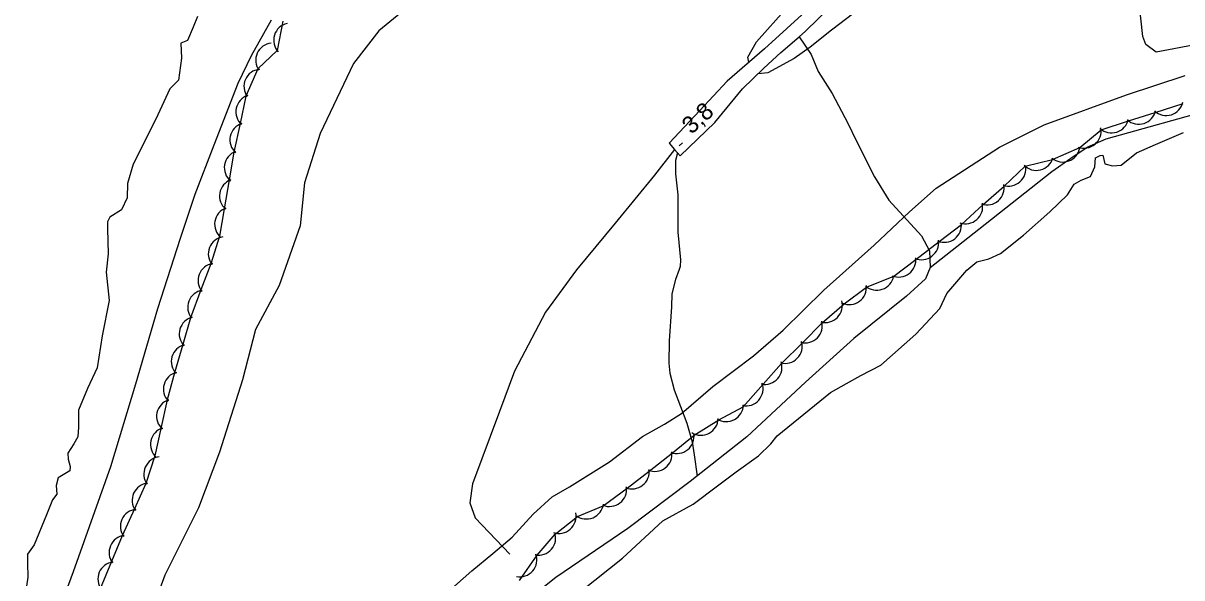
# Model space of a CAD drawing. Extents: x 643342 to 646936, y 5873857 to 5876103.
# Drawn here: x 644566.3 to 644768.3, y 5874065.4 to 5874162.1 of the extents above; entities that cross this region are included whole.
import ezdxf

# ---------------------------------------------------------------- set-up
doc = ezdxf.new("R2010")
doc.units = 0
for name, color, linetype in [('Niveau 2', 7, 'Continuous'), ('Niveau 21', 7, 'Continuous'), ('Niveau 22', 7, 'Continuous'), ('Niveau 3', 7, 'Continuous'), ('Niveau 4', 7, 'Continuous'), ('Niveau 44', 7, 'Continuous')]:
    doc.layers.add(name, color=color, linetype=linetype)

msp = doc.modelspace()

# ---------------------------------------------------------------- linework, layer by layer
at = {"layer": 'Niveau 2'}
for points in [[(644692.65, 5874156.21), (644694.14, 5874158.88), (644699.48, 5874164.83), (644707.75, 5874173.22), (644713.57, 5874178.44), (644722.46, 5874185), (644726.26, 5874189.75), (644732.94, 5874195.29), (644741.34, 5874199.21), (644749.71, 5874203.48), (644755.04, 5874205.3), (644757.78, 5874205.6), (644759.2, 5874204.9), (644759.81, 5874204.12)], [(644761.16, 5874202.41), (644761.28, 5874200.19), (644758.16, 5874197.32), (644744.89, 5874189.55), (644736.31, 5874183.44), (644730.75, 5874179.35), (644721.14, 5874171.56), (644707.22, 5874160.91), (644703.52, 5874157.93)], [(644662.34, 5874196.82), (644661.41, 5874195.84), (644649.56, 5874183.34), (644642.95, 5874174.73), (644635.35, 5874166.62), (644628.28, 5874160.81), (644623.9, 5874155.11), (644618.06, 5874142.91), (644615.35, 5874134.29), (644614.55, 5874126.78), (644610.92, 5874116.43), (644606.78, 5874108.75), (644604.5, 5874099.93), (644600.52, 5874087.37)], [(644781.37, 5874160.38), (644763.86, 5874157.08), (644762.05, 5874158.4), (644761.52, 5874159.82), (644760.82, 5874166.25), (644762.02, 5874169.59), (644764.15, 5874176.09), (644765.39, 5874183.98), (644768.73, 5874195.24)], [(644692.85, 5874155.34), (644692.65, 5874156.21)], [(644703.52, 5874157.93), (644700.73, 5874155.98), (644696.11, 5874153.45), (644694.43, 5874153.3)], [(644655.21, 5874076.54), (644658.5, 5874079.54), (644661.54, 5874081.28), (644668.55, 5874085.67), (644674.26, 5874090.06), (644678.09, 5874092.22), (644681.07, 5874094.08), (644686.52, 5874098.8), (644693.63, 5874104.14), (644698.81, 5874108.6), (644705.9, 5874115.6), (644714.7, 5874123.44), (644720.83, 5874129.23), (644725.51, 5874133.36), (644736.54, 5874140.52), (644744.36, 5874144.39), (644758.68, 5874149.65), (644768.9, 5874153.03)], [(644600.52, 5874087.37), (644596.85, 5874077.62), (644590.97, 5874065.9), (644587.51, 5874056.52), (644580.82, 5874046.15), (644576.13, 5874036.48), (644573.81, 5874030.4)], [(644612.95, 5874036.56), (644616.58, 5874040.86), (644620.47, 5874046.5), (644623.42, 5874050.12), (644626.23, 5874051.78), (644630.29, 5874052.55), (644633.28, 5874054.17), (644635.95, 5874056.88), (644638.47, 5874061.34), (644644.52, 5874066.64), (644648.16, 5874069.67), (644651.53, 5874072.5), (644655.21, 5874076.54)]]:
    msp.add_lwpolyline(points, dxfattribs=at)
at = {"layer": 'Niveau 21'}
for points in [[(644772.09, 5874211.29), (644767.46, 5874208.77), (644763.63, 5874206.66), (644754.24, 5874200.42), (644747.9, 5874197.27), (644742.34, 5874193.25), (644731.11, 5874185.07), (644719.85, 5874177.25), (644713.08, 5874172.18), (644704.64, 5874165.9), (644699.48, 5874161.2), (644695.53, 5874157.68), (644689.04, 5874152.04), (644684.27, 5874146.9), (644678.91, 5874141.19), (644679.88, 5874140.1), (644680.86, 5874139), (644686.92, 5874144.84), (644691.74, 5874150.68), (644695.45, 5874154.31), (644698.41, 5874157.04)], [(644698.41, 5874157.04), (644701.59, 5874159.76), (644702.7, 5874160.72), (644707.17, 5874165.11), (644714.04, 5874170.43), (644718.03, 5874173.49), (644722.83, 5874176.74), (644731.65, 5874182.7), (644739.15, 5874187.6), (644744.83, 5874191.63), (644749.51, 5874194.87), (644752.86, 5874197.17), (644759.01, 5874201.13), (644763.4, 5874203.75), (644766.9, 5874205.59), (644769.83, 5874207.26)]]:
    msp.add_lwpolyline(points, dxfattribs=at)
at = {"layer": 'Niveau 22'}
for points in [[(644609.52, 5874162.64), (644606.02, 5874156.43), (644603.7, 5874151.61), (644599.51, 5874140.84), (644596.2, 5874132.28), (644593.64, 5874124.61), (644589.7, 5874112.33), (644585.82, 5874099.22), (644581.46, 5874084.78), (644574.95, 5874066.5), (644570.62, 5874054.68)], [(644701.59, 5874159.76), (644703.72, 5874156.65), (644704.91, 5874153.69), (644707.34, 5874149.89), (644710.12, 5874144.71), (644711.55, 5874141.65), (644714.77, 5874135.32), (644717.22, 5874131.29), (644722.92, 5874125.06), (644724.31, 5874122.47), (644724.44, 5874119.52), (644723.65, 5874117.57), (644720.35, 5874114.56), (644711.16, 5874107.14), (644702.69, 5874099.55), (644692.48, 5874090.04), (644682.62, 5874082.21), (644671.71, 5874074.05), (644659.19, 5874065.52), (644650.55, 5874058.62), (644639.58, 5874049.87), (644630.72, 5874041.43), (644628.3, 5874038.97)], [(644724.44, 5874119.52), (644732.94, 5874126.24), (644745.66, 5874136.26), (644748.98, 5874138.6), (644751.84, 5874140.52), (644755.14, 5874141.98), (644769.08, 5874145.85), (644782.92, 5874149.7), (644792.04, 5874151.68), (644800.54, 5874152.91), (644806.09, 5874153.1), (644815.1, 5874153.01), (644824.97, 5874151.92), (644839.55, 5874149.58), (644858.61, 5874146.35), (644866.28, 5874145.85)], [(644679.88, 5874140.1), (644676.35, 5874135.66), (644669.5, 5874127.29), (644662.74, 5874119.15), (644657.35, 5874111.73), (644651.94, 5874101.47), (644649.34, 5874094.41), (644644.6, 5874081.85), (644644.16, 5874078.52), (644645.09, 5874075.89), (644651.15, 5874069.58)], [(644680.37, 5874139.55), (644680.05, 5874138.2), (644680.06, 5874135.86), (644680.42, 5874132.23), (644680.46, 5874125.69), (644680.93, 5874120.9), (644680.84, 5874119.72), (644680.69, 5874119.17), (644680.01, 5874117.45), (644679.4, 5874114.95), (644679.35, 5874112.7), (644678.94, 5874106.76), (644678.85, 5874102.84), (644679.05, 5874101.1), (644679.79, 5874098.24), (644682, 5874092.42), (644682.93, 5874089.13), (644683.27, 5874086.86), (644683.84, 5874083.17)]]:
    msp.add_lwpolyline(points, dxfattribs=at)
at = {"layer": 'Niveau 3'}
msp.add_line((644680.68, 5874140.73), (644681.27, 5874141.27), dxfattribs=at)
at = {"layer": 'Niveau 4'}
for points in [[(644596.69, 5874163.27), (644595.89, 5874161.43), (644594.91, 5874159.09), (644593.76, 5874158.64), (644593.86, 5874156.04), (644593.35, 5874152.21), (644591.82, 5874150.66), (644589.42, 5874145.37), (644585.46, 5874137.57), (644584.44, 5874134.17), (644584.41, 5874131.68), (644583.4, 5874129.58), (644581.37, 5874128.34), (644580.97, 5874127.48), (644580.95, 5874126.3), (644581.08, 5874121.93), (644580.75, 5874118.71)], [(644663.71, 5874063.26), (644670.81, 5874068.84), (644677.83, 5874075.36), (644683.14, 5874078.3), (644687.36, 5874081.5), (644690.59, 5874083.91), (644694.49, 5874086.73), (644696.68, 5874088.81), (644697.75, 5874090.21), (644707.05, 5874097.75), (644709.88, 5874099.3), (644712.36, 5874100.7), (644715.87, 5874102.54), (644721.93, 5874107.91), (644726.16, 5874112.42), (644727.37, 5874115), (644730.82, 5874119.08), (644732.59, 5874120.54), (644734.67, 5874121.07), (644736.72, 5874121.96), (644740.71, 5874125.15), (644745.34, 5874129.22), (644748.41, 5874132.2), (644749.55, 5874134.07), (644750.8, 5874134.77), (644752.4, 5874135.39), (644753.2, 5874137.11), (644753.31, 5874138.66), (644754.11, 5874139.08), (644754.58, 5874139.12), (644754.93, 5874137.62), (644756.26, 5874137.26), (644757.78, 5874137.39), (644760.45, 5874139.52), (644763.75, 5874140.99), (644768.66, 5874143.07)], [(644580.75, 5874118.71), (644581.28, 5874113.79), (644580.01, 5874107.65), (644579.18, 5874102.03), (644577.47, 5874098.45), (644575.89, 5874094.65), (644575.9, 5874091.7), (644575.8, 5874090.03), (644575.08, 5874088.79), (644574.03, 5874087.16), (644574.12, 5874086.11), (644574.46, 5874084.84), (644574.4, 5874084.12), (644572.38, 5874082.88), (644572.02, 5874081.55), (644572.14, 5874080.03), (644571.4, 5874079.02), (644570.32, 5874076.44), (644568.15, 5874071.17), (644566.99, 5874069.54), (644567, 5874068), (644567.09, 5874065.53), (644566.86, 5874063.97), (644566.08, 5874062.02)]]:
    msp.add_lwpolyline(points, dxfattribs=at)
at = {"layer": 'Niveau 44'}
for points in [[(644611.54, 5874162.47), (644610.55, 5874157.36), (644607.21, 5874154.17), (644605.12, 5874149.41), (644604.12, 5874144.66), (644603.01, 5874139.63), (644602.19, 5874134.84), (644601.32, 5874129.77), (644600.5, 5874124.99), (644598.97, 5874120.15), (644597.23, 5874115.62), (644595.44, 5874110.77), (644594.1, 5874106.11), (644592.68, 5874101.16), (644591.35, 5874096.49), (644590.26, 5874091.45), (644589.24, 5874086.7), (644587.64, 5874081.9), (644585.66, 5874077.47), (644583.55, 5874072.77), (644581.67, 5874068.29), (644579.68, 5874063.54)], [(644652.82, 5874064.97), (644655.88, 5874069.39), (644659.05, 5874073.06), (644662.93, 5874076.14), (644667.42, 5874078), (644671.62, 5874081.05), (644675.46, 5874084.03), (644679.51, 5874087.21), (644683.27, 5874090.29), (644687.58, 5874092.96), (644691.86, 5874095.26), (644695.33, 5874099.18), (644698.53, 5874102.83), (644702.2, 5874106.42), (644705.6, 5874109.88), (644709.44, 5874113.22), (644713.35, 5874116.1), (644718.1, 5874118), (644721.96, 5874120.94), (644726.05, 5874124.06), (644729.91, 5874127.01), (644733.7, 5874130.52), (644737.35, 5874133.72), (644741.05, 5874137.18), (644745.76, 5874138.35), (644750.55, 5874140.44), (644754.27, 5874143.56), (644759.07, 5874145.1), (644763.7, 5874146.57), (644768.6, 5874148.1)]]:
    msp.add_lwpolyline(points, dxfattribs=at)
for centre, start, end in [((644612.95, 5874159.16), 102.7911, 222.7691), ((644612.95, 5874159.16), 102.7911, 222.7691), ((644612.95, 5874159.16), 102.7911, 222.7691), ((644609.81, 5874155.67), 95.9227, 215.9006), ((644609.81, 5874155.67), 95.9227, 215.9006), ((644609.81, 5874155.67), 95.9227, 215.9006), ((644607.76, 5874151.11), 95.9227, 215.9006), ((644607.76, 5874151.11), 95.9227, 215.9006), ((644607.76, 5874151.11), 95.9227, 215.9006), ((644606.35, 5874146.68), 108.1804, 228.1584), ((644606.35, 5874146.68), 108.1804, 228.1584), ((644606.35, 5874146.68), 108.1804, 228.1584), ((644765.61, 5874149.03), 227.6864, 347.6644), ((644765.61, 5874149.03), 227.6864, 347.6644), ((644765.61, 5874149.03), 227.6864, 347.6644), ((644760.85, 5874147.51), 227.6864, 347.6644), ((644760.85, 5874147.51), 227.6864, 347.6644), ((644760.85, 5874147.51), 227.6864, 347.6644), ((644605.32, 5874141.78), 108.1804, 228.1584), ((644605.32, 5874141.78), 108.1804, 228.1584), ((644605.32, 5874141.78), 108.1804, 228.1584), ((644756.09, 5874146), 227.6864, 347.6644), ((644756.09, 5874146), 227.6864, 347.6644), ((644756.09, 5874146), 227.6864, 347.6644), ((644751.28, 5874143.35), 249.8984, 9.8764), ((644751.28, 5874143.35), 249.8984, 9.8764), ((644751.28, 5874143.35), 249.8984, 9.8764), ((644747.58, 5874140.92), 230.5222, 350.5001), ((644747.58, 5874140.92), 230.5222, 350.5001), ((644747.58, 5874140.92), 230.5222, 350.5001), ((644604.34, 5874136.94), 110.2919, 230.2698), ((644604.34, 5874136.94), 110.2919, 230.2698), ((644604.34, 5874136.94), 110.2919, 230.2698), ((644742.98, 5874139.47), 223.9868, 343.9647), ((644742.98, 5874139.47), 223.9868, 343.9647), ((644742.98, 5874139.47), 223.9868, 343.9647), ((644738.13, 5874136.74), 251.2351, 11.213), ((644738.13, 5874136.74), 251.2351, 11.213), ((644738.13, 5874136.74), 251.2351, 11.213), ((644603.5, 5874132.01), 110.2919, 230.2698), ((644603.5, 5874132.01), 110.2919, 230.2698), ((644603.5, 5874132.01), 110.2919, 230.2698), ((644734.37, 5874133.45), 251.2351, 11.213), ((644734.37, 5874133.45), 251.2351, 11.213), ((644734.37, 5874133.45), 251.2351, 11.213), ((644602.65, 5874127.08), 110.2919, 230.2698), ((644602.65, 5874127.08), 110.2919, 230.2698), ((644602.65, 5874127.08), 110.2919, 230.2698), ((644730.61, 5874130.15), 251.2351, 11.213), ((644730.61, 5874130.15), 251.2351, 11.213), ((644730.61, 5874130.15), 251.2351, 11.213), ((644726.91, 5874126.93), 247.3542, 7.3322), ((644726.91, 5874126.93), 247.3542, 7.3322), ((644726.91, 5874126.93), 247.3542, 7.3322), ((644601.55, 5874121.92), 98.9431, 218.921), ((644601.55, 5874121.92), 98.9431, 218.921), ((644601.55, 5874121.92), 98.9431, 218.921), ((644722.94, 5874123.9), 247.3542, 7.3322), ((644722.94, 5874123.9), 247.3542, 7.3322), ((644722.94, 5874123.9), 247.3542, 7.3322), ((644599.75, 5874117.25), 98.9431, 218.921), ((644599.75, 5874117.25), 98.9431, 218.921), ((644599.75, 5874117.25), 98.9431, 218.921), ((644718.96, 5874120.87), 247.3542, 7.3322), ((644718.96, 5874120.87), 247.3542, 7.3322), ((644718.96, 5874120.87), 247.3542, 7.3322), ((644715.13, 5874118.58), 229.0389, 349.0168), ((644715.13, 5874118.58), 229.0389, 349.0168), ((644715.13, 5874118.58), 229.0389, 349.0168), ((644710.35, 5874116.08), 246.357, 6.3349), ((644710.35, 5874116.08), 246.357, 6.3349), ((644710.35, 5874116.08), 246.357, 6.3349), ((644597.95, 5874112.59), 98.9431, 218.921), ((644597.95, 5874112.59), 98.9431, 218.921), ((644597.95, 5874112.59), 98.9431, 218.921), ((644706.15, 5874112.95), 255.5247, 15.5026), ((644706.15, 5874112.95), 255.5247, 15.5026), ((644706.15, 5874112.95), 255.5247, 15.5026), ((644596.47, 5874107.96), 104.0205, 223.9985), ((644596.47, 5874107.96), 104.0205, 223.9985), ((644596.47, 5874107.96), 104.0205, 223.9985), ((644702.64, 5874109.39), 255.5247, 15.5026), ((644702.64, 5874109.39), 255.5247, 15.5026), ((644702.64, 5874109.39), 255.5247, 15.5026), ((644595.09, 5874103.15), 104.0205, 223.9985), ((644595.09, 5874103.15), 104.0205, 223.9985), ((644595.09, 5874103.15), 104.0205, 223.9985), ((644699.14, 5874105.82), 255.5247, 15.5026), ((644699.14, 5874105.82), 255.5247, 15.5026), ((644699.14, 5874105.82), 255.5247, 15.5026), ((644695.61, 5874102.16), 258.71, 18.6879), ((644695.61, 5874102.16), 258.71, 18.6879), ((644695.61, 5874102.16), 258.71, 18.6879), ((644593.71, 5874098.34), 104.0205, 223.9985), ((644593.71, 5874098.34), 104.0205, 223.9985), ((644593.71, 5874098.34), 104.0205, 223.9985), ((644692.31, 5874098.41), 258.71, 18.6879), ((644692.31, 5874098.41), 258.71, 18.6879), ((644692.31, 5874098.41), 258.71, 18.6879), ((644592.53, 5874093.59), 107.8644, 227.8423), ((644592.53, 5874093.59), 107.8644, 227.8423), ((644592.53, 5874093.59), 107.8644, 227.8423), ((644688.88, 5874095.67), 238.2721, 358.2501), ((644688.88, 5874095.67), 238.2721, 358.2501), ((644688.88, 5874095.67), 238.2721, 358.2501), ((644591.48, 5874088.7), 107.8644, 227.8423), ((644591.48, 5874088.7), 107.8644, 227.8423), ((644591.48, 5874088.7), 107.8644, 227.8423), ((644684.48, 5874093.3), 238.2721, 358.2501), ((644684.48, 5874093.3), 238.2721, 358.2501), ((644684.48, 5874093.3), 238.2721, 358.2501), ((644680.27, 5874090.11), 249.2917, 9.2696), ((644680.27, 5874090.11), 249.2917, 9.2696), ((644680.27, 5874090.11), 249.2917, 9.2696), ((644676.42, 5874086.99), 247.748, 7.7259), ((644676.42, 5874086.99), 247.748, 7.7259), ((644676.42, 5874086.99), 247.748, 7.7259), ((644590.3, 5874083.53), 95.9014, 215.8793), ((644590.3, 5874083.53), 95.9014, 215.8793), ((644590.3, 5874083.53), 95.9014, 215.8793), ((644672.46, 5874083.94), 247.748, 7.7259), ((644672.46, 5874083.94), 247.748, 7.7259), ((644672.46, 5874083.94), 247.748, 7.7259), ((644588.26, 5874078.96), 95.9014, 215.8793), ((644588.26, 5874078.96), 95.9014, 215.8793), ((644588.26, 5874078.96), 95.9014, 215.8793), ((644668.51, 5874080.88), 247.748, 7.7259), ((644668.51, 5874080.88), 247.748, 7.7259), ((644668.51, 5874080.88), 247.748, 7.7259), ((644586.22, 5874074.4), 95.9014, 215.8793), ((644586.22, 5874074.4), 95.9014, 215.8793), ((644586.22, 5874074.4), 95.9014, 215.8793), ((644664.5, 5874078.7), 232.4658, 352.4438), ((644664.5, 5874078.7), 232.4658, 352.4438), ((644664.5, 5874078.7), 232.4658, 352.4438), ((644659.69, 5874076.17), 251.2848, 11.2628), ((644659.69, 5874076.17), 251.2848, 11.2628), ((644659.69, 5874076.17), 251.2848, 11.2628), ((644656.13, 5874072.38), 259.1128, 19.0907), ((644656.13, 5874072.38), 259.1128, 19.0907), ((644656.13, 5874072.38), 259.1128, 19.0907), ((644584.24, 5874069.85), 97.287, 217.2649), ((644584.24, 5874069.85), 97.287, 217.2649), ((644584.24, 5874069.85), 97.287, 217.2649), ((644652.86, 5874068.6), 259.1128, 19.0907), ((644652.86, 5874068.6), 259.1128, 19.0907), ((644652.86, 5874068.6), 259.1128, 19.0907), ((644582.3, 5874065.24), 97.287, 217.2649), ((644582.3, 5874065.24), 97.287, 217.2649), ((644582.3, 5874065.24), 97.287, 217.2649)]:
    msp.add_arc(centre, 3, start, end, dxfattribs=at)

# ---------------------------------------------------------------- texts
at = {"layer": 'Niveau 3'}
msp.add_text('3,8  ', height=3, rotation=42.3712, dxfattribs=at).set_placement((644682.83, 5874142.64))

doc.saveas('drawing.dxf')
